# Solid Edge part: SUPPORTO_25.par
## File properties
Subject: SUPPORTO_25
Author: Francesco
Template: Normal.par
Last saved by: Francesco
Revision: 8
Application: Solid Edge
Material: Alluminio, 1060
Stile della faccia: Alluminio
Stile di riempimento: ANSI38(Alluminio)
Stile virtuale: Alluminio lucidato
Coef. of Thermal Exp: 0.0
Thermal Conductivity: 221.0
Specific Heat: 920.0
Modulus of Elasticity: 68947570000.0
Poisson's Ratio: 0.33
Yield Stress: 27579028.0
Ultimate Stress: 68947570.0
Elongation: 0.0
Tipo di contenuto documento: 0
Densità: 2712,000 kg/m^3
Precisione: 0,990
Document Number: KR0136
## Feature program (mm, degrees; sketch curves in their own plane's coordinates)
sketch for "unnamed Protrusion 1" #1 plane through (0, 0, 0) normal (0, -1, 0) x-axis (1, 0, 0)
  circle centre (0.9359, 17.1523) radius 12.5
sketch for "unnamed Protrusion 1" #2 plane through (0, 0, 0) normal (0, -1, 0) x-axis (1, 0, 0)
  circle centre (-27.0341, 17.1523) radius 3.5
sketch for "unnamed Protrusion 1" #3 plane through (0, 0, 0) normal (0, -1, 0) x-axis (1, 0, 0)
  circle centre (28.9059, 17.1523) radius 3.5
sketch for "unnamed Protrusion 1" #4 plane through (0, 0, 0) normal (0, -1, 0) x-axis (1, 0, 0)
  line (-33.9641, 24.1523) -> (-33.9641, 10.1523)
  line (-33.9641, 10.1523) -> (-6.8509, -1.2696)
  line (35.8359, 10.1523) -> (8.7227, -1.2696)
  line (35.8359, 24.1523) -> (35.8359, 10.1523)
  line (35.8359, 24.1523) -> (8.7227, 35.5742)
  arc centre (0.9359, 17.1523) radius 20 from (-6.8509, 35.5742) to (8.7227, 35.5742) cw
  line (-33.9641, 24.1523) -> (-6.8509, 35.5742)
extrude "unnamed Protrusion 1" add finite 10 along +normal
sketch for "ExtrudedProtrusion_7" #1 plane through (0.9359, 0, 17.1523) normal (0, 1, 0) x-axis (-0.921565, 0, -0.388224)
  circle centre (0, 0) radius 12.5
sketch for "ExtrudedProtrusion_7" #2 plane through (0.9359, 0, 17.1523) normal (0, 1, 0) x-axis (-0.921565, 0, -0.388224)
  circle centre (0, 0) radius 20
extrude "ExtrudedProtrusion_7" add finite 15 along +normal
sketch for "ExtrudedProtrusion_8" plane through (0, 0, 0) normal (1, 0, 0) x-axis (0, 1, 0)
  arc centre (2.5483, -17.9622) radius 56.5036 from (-10, 37.1304) to (15, 37.1523) cw
  line (15, 37.1523) -> (15, 35.1523)
  line (15, 35.1523) -> (-10, 35.1304)
  line (-10, 37.1304) -> (-10, 35.1304)
extrude "ExtrudedProtrusion_8" add finite 15 symmetric
fillet "Rotondo_5" radius 6
sketch for "ExtrudedCutout_6" plane through (0.9359, 15, 17.1523) normal (0, 1, 0) x-axis (-1, 0, 0)
  line (-0.5553, 23.2331) -> (-0.5553, 6.9738)
  line (-0.5553, 6.9738) -> (1.4447, 6.9738)
  line (1.4447, 6.9738) -> (1.4447, 23.2331)
  line (1.4447, 23.2331) -> (-0.5553, 23.2331)
extrude "ExtrudedCutout_6" cut finite 76.0963 along -normal
chamfer "Smusso_2" setback 0.5
chamfer "Smusso_3" setback 0.5
sketch for "Foro_14" plane through (17.5587, 0, 0) normal (1, 0, 0) x-axis (0, 1, 0)
  hole centre (7.5, 35.1523) bore radius 2
hole "Foro_14" diameter 4 through
sketch for "ExtrudedCutout_7" plane through (17.5587, 0, 0) normal (1, 0, 0) x-axis (0, 1, 0)
  circle centre (7.5, 35.1523) radius 3.4288
extrude "ExtrudedCutout_7" cut finite 10.5 along -normal
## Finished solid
Body 1: solid body, 32 faces, 80 edges, 46 vertices.
  Faces by surface: plane 13, cylinder 10, cone 6, blend 3
  Edges by curve: line 31, circle 27, intersection 22
Bounding box of the edges (mm; curved faces can reach further): 69.800 x 25.000 x 41.389, from (-33.9641, -10, -2.8477) to (35.8359, 15, 38.5413).
Cylindrical faces by radius (mm): R2 x2, R3.4288 x1, R3.5 x2, R12.5 x1, R20 x2, R56.5036 x2
Conical faces (half-angle, radius in mm at the cone's reference point): 45 deg R3.5 x2, 45 deg R4 x2, 45 deg R13 x2
Planar faces by outward normal: +x 3, +y 3, -x 2, -y 1, oblique 4
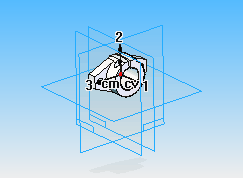
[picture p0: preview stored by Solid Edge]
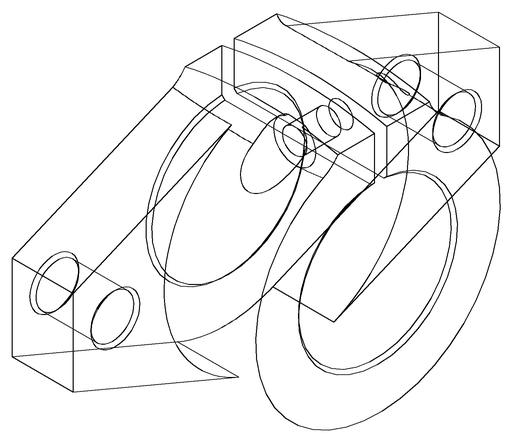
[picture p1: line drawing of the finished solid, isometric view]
